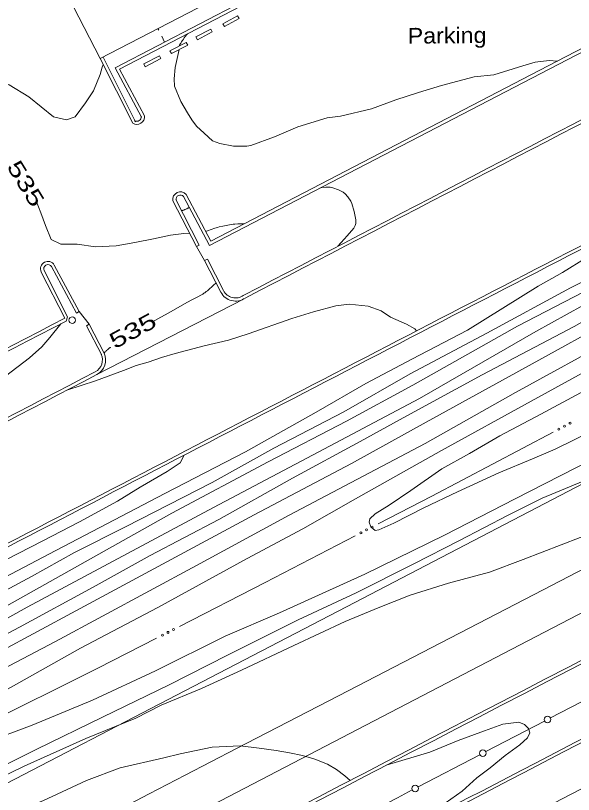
# Model space of a CAD drawing. Extents: x 2361284 to 2366480, y 6976556 to 6985346.
# Drawn here: x 2363068.1 to 2363237.5, y 6978434.8 to 6978671.2 of the extents above; entities that cross this region are included whole.
import ezdxf
from ezdxf.enums import TextEntityAlignment as Align

# ---------------------------------------------------------------- set-up
doc = ezdxf.new("R2010")
doc.units = 0
doc.header["$LTSCALE"] = 1.9
for name, color, linetype, lineweight in [('12', 7, 'Continuous', 13), ('13', 7, 'Continuous', 13), ('14', 7, 'Continuous', 13), ('19', 7, 'Continuous', 13), ('21', 7, 'Continuous', 13), ('3', 7, 'Continuous', 13), ('4', 7, 'Continuous', 13), ('5', 7, 'Continuous', 13), ('7', 7, 'Continuous', 13)]:
    doc.layers.add(name, color=color, linetype=linetype, lineweight=lineweight)

msp = doc.modelspace()

# ---------------------------------------------------------------- linework, layer by layer
at = {"layer": '12'}
for points in [[(2363425.131, 6978674.37), (2363410.482, 6978666.74), (2363395.262, 6978658.375), (2363383.212, 6978651.901), (2363368.635, 6978644.111), (2363350.983, 6978633.733), (2363328, 6978620.233), (2363315.46, 6978613.894), (2363293.258, 6978602.281), (2363261.983, 6978585.954), (2363228.945, 6978567.679), (2363192.752, 6978547.753), (2363170.1, 6978535.207), (2363140.527, 6978519.605), (2363114.03, 6978505.403), (2363086.361, 6978490.518), (2363062.949, 6978478.006), (2363045.723, 6978468.991), (2363032.41, 6978461.884)], [(2363165.952, 6978601.161), (2363166.941, 6978602.34), (2363168.732, 6978604.327), (2363170.761, 6978606.678), (2363171.201, 6978607.487), (2363171.367, 6978608.058), (2363171.407, 6978609.214), (2363170.894, 6978611.689), (2363170.169, 6978614.143), (2363169.862, 6978614.864), (2363168.98, 6978616.191), (2363168.121, 6978617.068), (2363167.485, 6978617.547), (2363166.069, 6978618.324), (2363164.431, 6978618.895), (2363163.58, 6978619.06), (2363162.301, 6978619.138), (2363161.058, 6978618.994), (2363160.464, 6978618.831)], [(2363120.862, 6978605.152), (2363119.104, 6978604.996), (2363115.128, 6978604.568), (2363109.909, 6978603.378), (2363104.248, 6978602.344), (2363098.567, 6978601.27), (2363092.301, 6978600.951), (2363086.763, 6978601.788), (2363081.761, 6978601.81), (2363078.848, 6978603.203), (2363077.108, 6978607.437), (2363075.711, 6978611.254), (2363074.317, 6978614.891)], [(2363120.818, 6978612.943), (2363120.664, 6978612.857), (2363120.586, 6978612.816), (2363120.469, 6978612.755), (2363120.351, 6978612.697), (2363120.291, 6978612.668), (2363120.056, 6978612.558), (2363119.939, 6978612.504), (2363119.762, 6978612.425), (2363119.585, 6978612.346), (2363119.496, 6978612.308), (2363119.317, 6978612.233), (2363119.228, 6978612.196), (2363119.093, 6978612.143), (2363118.912, 6978612.073), (2363118.821, 6978612.04), (2363118.685, 6978611.991), (2363118.547, 6978611.944), (2363118.478, 6978611.921)], [(2363137.387, 6978607.941), (2363136.836, 6978607.98), (2363136.56, 6978607.991), (2363136.146, 6978607.996), (2363135.526, 6978607.973), (2363134.615, 6978607.896), (2363134.161, 6978607.846), (2363133.481, 6978607.759), (2363132.464, 6978607.596), (2363131.449, 6978607.395), (2363130.943, 6978607.279), (2363129.897, 6978607.015), (2363129.379, 6978606.873), (2363128.609, 6978606.647), (2363127.464, 6978606.276), (2363126.331, 6978605.863), (2363125.767, 6978605.639)], [(2363253.996, 6978607.619), (2363253.283, 6978605.821), (2363248.717, 6978602.228), (2363241.34, 6978597.638), (2363234.103, 6978593.16), (2363226.762, 6978589.02), (2363205.247, 6978575.723), (2363188.419, 6978566.924), (2363174.43, 6978559.51), (2363159.371, 6978550.766), (2363137.904, 6978538.791), (2363113.334, 6978526.107), (2363078.126, 6978507.682), (2363030.81, 6978482.841), (2363007.915, 6978470.651)], [(2363109.658, 6978578.215), (2363111.235, 6978579.115), (2363114.403, 6978580.89), (2363120.282, 6978584.147), (2363121.627, 6978584.875), (2363123.426, 6978585.835), (2363124.321, 6978586.325), (2363124.887, 6978586.66), (2363125.254, 6978586.898), (2363125.495, 6978587.063), (2363125.967, 6978587.407), (2363126.314, 6978587.675), (2363126.992, 6978588.234), (2363127.652, 6978588.818), (2363128.084, 6978589.217), (2363128.937, 6978590.029)], [(2363189.808, 6978575.477), (2363189.331, 6978576.142), (2363186.748, 6978577.508), (2363181.918, 6978579.622), (2363179.09, 6978581.515), (2363175.077, 6978582.957), (2363169.319, 6978583.612), (2363165.314, 6978583.094), (2363158.531, 6978581.279), (2363151.92, 6978579.206), (2363138.644, 6978574.57), (2363132.732, 6978572.664), (2363125.327, 6978570.923), (2363116.509, 6978568.639), (2363112.391, 6978567.441), (2363108.304, 6978566.012), (2363104.684, 6978564.988), (2363100.797, 6978563.481), (2363092.277, 6978560.329), (2363083.644, 6978557.476)], [(2363094.957, 6978568.754), (2363095.165, 6978568.978), (2363095.27, 6978569.089), (2363095.428, 6978569.254), (2363095.588, 6978569.416), (2363095.669, 6978569.497), (2363095.833, 6978569.655), (2363095.916, 6978569.733), (2363096.043, 6978569.847), (2363096.157, 6978569.947), (2363096.215, 6978569.997), (2363096.302, 6978570.069), (2363096.436, 6978570.176), (2363096.572, 6978570.28), (2363096.641, 6978570.331), (2363096.736, 6978570.398), (2363096.8, 6978570.441), (2363096.843, 6978570.469), (2363096.901, 6978570.505), (2363096.93, 6978570.523)], [(2363245.276, 6978515.02), (2363222.22, 6978506.112), (2363212.015, 6978502.204), (2363199.518, 6978498.865), (2363187.89, 6978495.285), (2363178.197, 6978491.441), (2363168.135, 6978487.266), (2363152.574, 6978479.938), (2363136.654, 6978472.546), (2363124.526, 6978466.89), (2363112.284, 6978461.853), (2363104.621, 6978457.97), (2363089.379, 6978451.756), (2363070.637, 6978443.367), (2363050.648, 6978433.696)]]:
    msp.add_lwpolyline(points, dxfattribs=at)
at = {"layer": '13'}
for points in [[(2363466.464, 6978693.163), (2363427.882, 6978671.135), (2363406.518, 6978659.812), (2363378.846, 6978645.158), (2363355.135, 6978632.452), (2363330.817, 6978619.5), (2363302.789, 6978603.332), (2363273.639, 6978586.335), (2363250.48, 6978573.553), (2363219.818, 6978556.721), (2363192.452, 6978541.33), (2363151.159, 6978519.537), (2363122.982, 6978504.268), (2363080.158, 6978481.2), (2363045.956, 6978463.343), (2363028.606, 6978453.868), (2362997.225, 6978435.868)], [(2363471.837, 6978691.884), (2363433.081, 6978669.065), (2363388.829, 6978643.763), (2363361.558, 6978630.143), (2363335.038, 6978616.29), (2363304.423, 6978598.767), (2363283.358, 6978586.648), (2363254.449, 6978570.531), (2363224.593, 6978554.106), (2363197.365, 6978539.137), (2363171.312, 6978524.538), (2363155.277, 6978515.405), (2363138.423, 6978506.345), (2363111.253, 6978491.475), (2363087.769, 6978479.162), (2363067.447, 6978467.717), (2363051.708, 6978459.007), (2363041.356, 6978452.82), (2363025.578, 6978443.038), (2363017.156, 6978436.918)], [(2363404.842, 6978677.178), (2363386.759, 6978666.934), (2363370.561, 6978658.34), (2363349.169, 6978646.756), (2363326.951, 6978634.904), (2363305.503, 6978622), (2363284.28, 6978610.557), (2363263.345, 6978599.367), (2363243.325, 6978588.707), (2363220.507, 6978576.858), (2363188.725, 6978558.956), (2363168.577, 6978548.073), (2363144.804, 6978535.717), (2363115.53, 6978520.148), (2363063.804, 6978491.124), (2363027.404, 6978471.927), (2362989.536, 6978451.437)], [(2363420.847, 6978676.89), (2363400.664, 6978665.546), (2363383.778, 6978656.545), (2363364.35, 6978646.78), (2363346.604, 6978637.691), (2363320.48, 6978623.292), (2363297.872, 6978610.297), (2363272.542, 6978596.555), (2363249.823, 6978583.698), (2363237.629, 6978576.751), (2363209.735, 6978562.136), (2363186.853, 6978549.667), (2363172.647, 6978541.912), (2363152.141, 6978530.756), (2363129.77, 6978518.193), (2363108.943, 6978507.265), (2363091.583, 6978497.669), (2363069.237, 6978485.515), (2363053.812, 6978477.479), (2363033.78, 6978467.117), (2363018.575, 6978459.122), (2362992.386, 6978445.153)], [(2363411.158, 6978675.608), (2363398.63, 6978669.077), (2363374.655, 6978656.739), (2363360.176, 6978649.281), (2363331.118, 6978634.134), (2363304.774, 6978618.643), (2363274.153, 6978601.67), (2363249.808, 6978588.469), (2363226.012, 6978575.331), (2363190.672, 6978554.994), (2363156.533, 6978536.848), (2363128.204, 6978521.888), (2363071.559, 6978491.597), (2363048.758, 6978478.971), (2362991.135, 6978448.391)], [(2363375.65, 6978670.939), (2363375.344, 6978669.496), (2363373.266, 6978667.316), (2363369.52, 6978664.62), (2363363.374, 6978660.992), (2363358.271, 6978658.133), (2363348.567, 6978652.291), (2363333.03, 6978642.352), (2363312.867, 6978631.06), (2363295.42, 6978621.024), (2363282.312, 6978613.489), (2363251.326, 6978596.013), (2363236.606, 6978588.503), (2363211.206, 6978574.75), (2363187.872, 6978562.399), (2363167.69, 6978550.905), (2363146.465, 6978539.844), (2363127.722, 6978529.504), (2363101.439, 6978515.953), (2363085.992, 6978508.236), (2363072.94, 6978500.912), (2363041.639, 6978484.123), (2362987.669, 6978454.279)], [(2363117.703, 6978661.906), (2363117.802, 6978662.085), (2363117.868, 6978662.204), (2363118.004, 6978662.441), (2363118.073, 6978662.558), (2363118.213, 6978662.792), (2363118.356, 6978663.024), (2363118.452, 6978663.178), (2363118.648, 6978663.485), (2363118.811, 6978663.733), (2363118.921, 6978663.897), (2363118.996, 6978664.005), (2363119.146, 6978664.22), (2363119.261, 6978664.381), (2363119.338, 6978664.487), (2363119.494, 6978664.698), (2363119.573, 6978664.803), (2363119.733, 6978665.012), (2363119.895, 6978665.219), (2363120.005, 6978665.357), (2363120.078, 6978665.448), (2363120.227, 6978665.63)], [(2363232.572, 6978657.318), (2363230.07, 6978657.514), (2363225.815, 6978657.024), (2363222.115, 6978655.918), (2363213.32, 6978653.145), (2363207.335, 6978652.579), (2363197.351, 6978649.923), (2363190.44, 6978647.807), (2363183.57, 6978645.641), (2363176.147, 6978642.871), (2363166.737, 6978640.681), (2363162.651, 6978640.162), (2363153.717, 6978637.427), (2363146.646, 6978634.37), (2363139.471, 6978631.722), (2363138.293, 6978631.5), (2363134.212, 6978631.501), (2363130.055, 6978632.312), (2363127.877, 6978633.101), (2363125.334, 6978635.427), (2363123.043, 6978637.566), (2363121.566, 6978639.502), (2363120.306, 6978641.63), (2363118.252, 6978645.11), (2363116.348, 6978649.732), (2363116.177, 6978651.952), (2363116.474, 6978655.444), (2363117.743, 6978660.846)], [(2363094.663, 6978656.357), (2363094.301, 6978655.543), (2363093.744, 6978653.288), (2363091.681, 6978648.288), (2363089.285, 6978644.685), (2363086.175, 6978640.485), (2363083.544, 6978639.5), (2363079.544, 6978640.402), (2363072.066, 6978646.551), (2363066.102, 6978650.185), (2363062.282, 6978652.239), (2363058.378, 6978654.602), (2363055.115, 6978657.021), (2363048.092, 6978659.444)], [(2363416.648, 6978618.916), (2363397.786, 6978610.617), (2363380.297, 6978602.909), (2363363.089, 6978595.286), (2363343.764, 6978585.172), (2363322.354, 6978575.507), (2363296.819, 6978562.324), (2363267.053, 6978548.07), (2363247.313, 6978538.522), (2363219.785, 6978524.489), (2363198.288, 6978513.493), (2363174.07, 6978501.614), (2363148.229, 6978489.916), (2363131.686, 6978482.83), (2363110.495, 6978472.297), (2363091.408, 6978463.445), (2363073.079, 6978455.781), (2363058.908, 6978450.595)], [(2363081.821, 6978577.62), (2363078.501, 6978573.438), (2363076.077, 6978570.645), (2363072.309, 6978567.27), (2363064.993, 6978561.73), (2363053.641, 6978554.361), (2363045.787, 6978548.506), (2363038.227, 6978542.254), (2363024.622, 6978533.124), (2363013.072, 6978526.674), (2362997.711, 6978518.358), (2362987.423, 6978512.718), (2362976.815, 6978507.348), (2362964.075, 6978500.827)], [(2363243.021, 6978545.031), (2363231.952, 6978539.617), (2363225.07, 6978536.63), (2363214.81, 6978532.382), (2363202.284, 6978526.593), (2363192.048, 6978521.775), (2363182.883, 6978517.077), (2363178.312, 6978515.084), (2363177.214, 6978514.863), (2363175.934, 6978515.961), (2363175.471, 6978517.367), (2363175.671, 6978518.42), (2363177.266, 6978519.955), (2363181.45, 6978522.605), (2363188.069, 6978526.998), (2363197.507, 6978533.598), (2363205.923, 6978538.298), (2363215.103, 6978543.636), (2363227.601, 6978550.145), (2363249.022, 6978561.74)], [(2363119.293, 6978537.764), (2363118.025, 6978535.462), (2363114.06, 6978532.764), (2363105.925, 6978528.057), (2363098.984, 6978523.811), (2363087.474, 6978517.541), (2363076.287, 6978511.744), (2363054.005, 6978500.292), (2363036.704, 6978490.886), (2363022.436, 6978483.261), (2363009.254, 6978476.035), (2363003.792, 6978473.092)], [(2363240.425, 6978529.836), (2363227.963, 6978524.677), (2363217.652, 6978519.539), (2363202.834, 6978511.858), (2363189, 6978504.726), (2363171.504, 6978495.999), (2363153.82, 6978487.769), (2363132.36, 6978477.096), (2363114.715, 6978468.097), (2363094.498, 6978458.194), (2363074.508, 6978448.524), (2363054.502, 6978438.573)], [(2363182.847, 6978421.912), (2363187.406, 6978425.196), (2363193.554, 6978428.755), (2363198.462, 6978432.141), (2363203.617, 6978435.801), (2363208.109, 6978439.833), (2363212.209, 6978442.873), (2363216.745, 6978446.606), (2363221.185, 6978449.818), (2363223.455, 6978451.941), (2363224.22, 6978453.478), (2363223.858, 6978454.785), (2363222.626, 6978456.023), (2363220.849, 6978456.706), (2363216.025, 6978456.12), (2363210.483, 6978454.098), (2363202.401, 6978451.171), (2363193.834, 6978447.648), (2363180.621, 6978443.642)], [(2363169.644, 6978439.028), (2363168.061, 6978440.423), (2363165.522, 6978442.359), (2363162.777, 6978443.943), (2363158.882, 6978445.526), (2363155.212, 6978446.551), (2363151.265, 6978447.363), (2363147.207, 6978448.075), (2363141.98, 6978448.835), (2363136.223, 6978449.49), (2363127.796, 6978449.1), (2363117.985, 6978447.087), (2363113.086, 6978445.94), (2363099.794, 6978442.824), (2363089.621, 6978439.017), (2363076.307, 6978432.87), (2363060.476, 6978426.739), (2363049.242, 6978422.762), (2363035.932, 6978417.435), (2363021.666, 6978411.769), (2363012.303, 6978407.75)]]:
    msp.add_lwpolyline(points, dxfattribs=at)
at = {"layer": '14'}
for points in [[(2363949.629, 6978887.968), (2363929.935, 6978874.907), (2363890.416, 6978848.983), (2363868.159, 6978834.534), (2363853.276, 6978824.971), (2363823.411, 6978805.994), (2363812.654, 6978799.246), (2363791.042, 6978785.916), (2363769.312, 6978772.782), (2363754.767, 6978764.121), (2363725.557, 6978746.99), (2363693.768, 6978728.641), (2363677.819, 6978719.566), (2363653.804, 6978706.125), (2363629.648, 6978692.939), (2363617.507, 6978686.459), (2363544.112, 6978647.817), (2363507.33, 6978628.659), (2363367.402, 6978556.134), (2363223.565, 6978481.393), (2363026.986, 6978379.118)], [(2363951.494, 6978832.723), (2363916.041, 6978809.685), (2363857.621, 6978772.577), (2363781.115, 6978725.377), (2363714.322, 6978686.016), (2363680.485, 6978667.097), (2363570.079, 6978608.155), (2363462.054, 6978552.184), (2363320.548, 6978478.375), (2363145.373, 6978387.445), (2363047.939, 6978336.875)], [(2363021.389, 6978389.336), (2363050.467, 6978404.567), (2363065.01, 6978412.173), (2363086.833, 6978423.568), (2363108.666, 6978434.943), (2363119.587, 6978440.622), (2363135.102, 6978448.676), (2363166.147, 6978464.756), (2363228.252, 6978496.885), (2363248.945, 6978507.613), (2363259.287, 6978512.984), (2363294.18, 6978531.142), (2363340.693, 6978555.376), (2363363.954, 6978567.483), (2363374.788, 6978573.111), (2363396.467, 6978584.346), (2363439.836, 6978606.794), (2363461.508, 6978618.043), (2363470.134, 6978622.537), (2363475.881, 6978625.539), (2363487.368, 6978631.558), (2363504.583, 6978640.615), (2363516.051, 6978646.668), (2363538.975, 6978658.801)]]:
    msp.add_lwpolyline(points, dxfattribs=at)
at = {"layer": '19'}
for p, q in [((2363111.547, 6978666.688), (2363111.282, 6978667.225)), ((2363113.301, 6978663.104), (2363112.424, 6978664.896))]:
    msp.add_line(p, q, dxfattribs=at)
at = {"layer": '21'}
for points in [[(2363231.253, 6978544.749), (2363194.436, 6978525.328), (2363178.125, 6978516.862)], [(2363171.17, 6978513.246), (2363143.832, 6978499.056), (2363117.837, 6978485.757)], [(2363110.861, 6978482.192), (2363093.057, 6978473.091), (2363057.244, 6978455.271)]]:
    msp.add_lwpolyline(points, dxfattribs=at)
for centre in [(2363234.716, 6978546.575), (2363236.415, 6978547.471), (2363233.018, 6978545.679), (2363176.348, 6978515.937), (2363172.94, 6978514.168), (2363174.644, 6978515.053), (2363116.05, 6978484.849), (2363112.631, 6978483.101), (2363114.341, 6978483.975)]:
    msp.add_circle(centre, 0.3, dxfattribs=at)
at = {"layer": '3'}
for p, q in [((2363135.441, 6978671.133), (2363130.984, 6978668.69)), ((2363135.906, 6978670.293), (2363131.449, 6978667.851)), ((2363135.441, 6978671.133), (2363135.906, 6978670.293)), ((2363127.338, 6978667.036), (2363122.801, 6978664.672)), ((2363127.338, 6978667.036), (2363127.786, 6978666.187)), ((2363130.984, 6978668.69), (2363131.449, 6978667.851)), ((2363122.801, 6978664.672), (2363123.249, 6978663.823)), ((2363127.786, 6978666.187), (2363123.249, 6978663.823)), ((2363119.886, 6978663.034), (2363114.94, 6978660.487)), ((2363120.331, 6978662.184), (2363115.384, 6978659.636)), ((2363119.886, 6978663.034), (2363120.331, 6978662.184)), ((2363114.94, 6978660.487), (2363115.384, 6978659.636)), ((2363111.745, 6978658.947), (2363106.989, 6978656.471)), ((2363112.193, 6978658.097), (2363107.436, 6978655.622)), ((2363111.745, 6978658.947), (2363112.193, 6978658.097)), ((2363106.989, 6978656.471), (2363107.436, 6978655.622)), ((2363126.298, 6978597.274), (2363125.441, 6978596.836)), ((2363137.453, 6978585.23), (2363092.719, 6978562.204)), ((2363137.213, 6978586.224), (2363137.325, 6978586.293)), ((2363137.771, 6978585.442), (2363137.768, 6978585.441)), ((2363086.542, 6978580.875), (2363087.387, 6978581.323)), ((2363090.404, 6978577.482), (2363087.387, 6978581.323)), ((2363089.548, 6978577.033), (2363090.404, 6978577.482)), ((2363187.36, 6978574.214), (2363187.357, 6978574.212)), ((2363187.801, 6978573.361), (2363187.8, 6978573.36)), ((2363092.274, 6978563.054), (2363092.267, 6978563.05)), ((2363092.718, 6978562.202), (2363092.719, 6978562.203))]:
    msp.add_line(p, q, dxfattribs=at)
for points in [[(2363011.072, 6978409.979), (2363168.573, 6978491.77), (2363368.216, 6978595.675), (2363555.651, 6978691.931), (2363594.46, 6978712.53), (2363671.163, 6978755.453), (2363729.15, 6978790.847), (2363782.829, 6978826.545), (2363808.985, 6978845.429), (2363827.885, 6978860.013), (2363864.479, 6978890.628), (2363923.502, 6978944.293), (2363947.382, 6978968.611)], [(2363106.232, 6978640.619), (2363106.338, 6978640.307), (2363098.343, 6978655.322), (2363175.407, 6978695.437), (2363288.34, 6978753.653), (2363332.165, 6978776.451), (2363340.338, 6978761.439), (2363343.881, 6978763.293), (2363343.933, 6978763.321)], [(2363107.182, 6978640.755), (2363107.183, 6978640.755), (2363099.647, 6978654.914), (2363175.846, 6978694.581), (2363288.778, 6978752.798), (2363331.777, 6978775.167), (2363339.951, 6978760.154), (2363344.329, 6978762.447), (2363344.329, 6978762.446)], [(2363353.066, 6978738.291), (2363353.007, 6978738.457), (2363360.778, 6978722.661), (2363232.792, 6978656.35), (2363126.908, 6978601.42), (2363118.985, 6978616.416), (2363119.095, 6978616.247)], [(2363352.142, 6978738.029), (2363352.141, 6978738.029), (2363359.504, 6978723.079), (2363232.354, 6978657.206), (2363127.316, 6978602.714), (2363119.831, 6978616.864), (2363119.831, 6978616.864)], [(2363093.757, 6978658.158), (2363103.643, 6978638.521), (2363103.644, 6978638.521)], [(2363094.612, 6978658.586), (2363104.5, 6978638.949), (2363104.175, 6978639.321)], [(2363115.851, 6978614.946), (2363115.849, 6978614.946), (2363122.95, 6978601.072)], [(2363116.791, 6978615.137), (2363116.705, 6978615.384), (2363123.806, 6978601.51)], [(2363123.806, 6978601.51), (2363122.95, 6978601.072), (2363125.441, 6978596.836)], [(2363125.441, 6978596.836), (2363130.363, 6978587.243), (2363130.363, 6978587.242)], [(2363126.298, 6978597.274), (2363131.219, 6978587.681), (2363131.217, 6978587.681)], [(2363076.738, 6978593.756), (2363076.728, 6978593.773), (2363083.842, 6978579.739), (2363083.426, 6978578.448)], [(2363086.542, 6978580.875), (2363078.976, 6978595.015), (2363078.996, 6978594.973)], [(2363087.387, 6978581.323), (2363079.822, 6978595.463), (2363079.822, 6978595.462)], [(2363075.875, 6978593.336), (2363075.872, 6978593.335), (2363082.986, 6978579.301), (2363082.985, 6978579.301)], [(2363094.958, 6978568.755), (2363094.957, 6978568.754), (2363090.404, 6978577.482)], [(2363094.082, 6978568.362), (2363094.102, 6978568.306), (2363089.548, 6978577.033)]]:
    msp.add_lwpolyline(points, dxfattribs=at)
for centre, radius, start, end in [((2446851.432, 6817441.355), 181592.243, 117.35268, 117.45168), ((2446851.433, 6817441.355), 181591.283, 117.35268, 117.45168), ((2342834.51, 7017985.293), 44356.191, 297.31294, 297.61226), ((2342834.51, 7017985.293), 44357.151, 297.31294, 297.61226), ((2510756.167, 6694462.226), 320038.438, 117.37709, 117.46624), ((2510756.166, 6694462.227), 320037.476, 117.37709, 117.46624), ((2363104.912, 6978640.431), 2.293, 236.42127, 8.10639), ((2363104.912, 6978640.431), 1.333, 236.42125, 8.10637), ((2363118.084, 6978615.399), 2.279, 39.98858, 191.45927), ((2363118.084, 6978615.399), 1.319, 39.98858, 191.45927), ((2363077.892, 6978594.319), 2.244, 30.64163, 205.97974), ((2363077.892, 6978594.319), 1.284, 30.64164, 205.97975), ((2363134.845, 6978589.546), 5.04, 207.20297, 305.48306), ((2363134.845, 6978589.546), 4.08, 207.20298, 305.48306), ((2416815.134, 6874672.847), 116977.327, 117.34441, 117.41385), ((2416815.134, 6874672.849), 116976.366, 117.34441, 117.41385), ((2290091.034, 7119171.363), 158463.343, 297.386, 297.46988), ((2290091.035, 7119171.361), 158464.302, 297.386, 297.46988), ((2363090.327, 6978566.679), 4.115, 298.12336, 24.15065), ((2363090.327, 6978566.679), 5.075, 298.12336, 24.15065), ((2341888.702, 7019227.765), 45860.77, 297.36056, 297.53863), ((2341888.701, 7019227.765), 45861.73, 297.36056, 297.53863), ((2341214.887, 7020680.278), 47627.312, 297.27734, 297.63097), ((2341214.887, 7020680.278), 47628.272, 297.27734, 297.63097)]:
    msp.add_arc(centre, radius, start, end, dxfattribs=at)
at = {"layer": '4'}
msp.add_circle((2363085.275, 6978578.733), 1, dxfattribs=at)
at = {"layer": '5'}
for p, q in [((2363249.166, 6978467.735), (2363230.438, 6978457.987)), ((2363228.676, 6978457.071), (2363210.823, 6978447.77)), ((2363209.002, 6978446.822), (2363190.274, 6978437.074))]:
    msp.add_line(p, q, dxfattribs=at)
msp.add_lwpolyline([(2363188.512, 6978436.157), (2363183.984, 6978433.804), (2363170.651, 6978426.877)], dxfattribs=at)
for centre in [(2363229.559, 6978457.527), (2363209.938, 6978447.313), (2363189.394, 6978436.619)]:
    msp.add_circle(centre, 1, dxfattribs=at)
at = {"layer": '7'}
msp.add_lwpolyline([(2363054.534, 6978733.96), (2363093.757, 6978658.158), (2363253.908, 6978741.025), (2363251.687, 6978745.325), (2363286.667, 6978763.399), (2363281.899, 6978772.633), (2363321.993, 6978793.336), (2363211.982, 6979006.392), (2363135.971, 6978967.146), (2363213.89, 6978816.239)], close=True, dxfattribs=at)

# ---------------------------------------------------------------- texts
at = {"layer": '12', "width": 1.4}
for rotation, p in [(301.554, (2363069.13, 6978618.943)), (28.509, (2363104.776, 6978573.432))]:
    msp.add_text(' 535 ', height=4.8, rotation=rotation, dxfattribs=at).set_placement(p, align=Align.CENTER)
at = {"layer": '3', "width": 1.1}
msp.add_text('Parking', height=4.799, rotation=0.545, dxfattribs=at).set_placement((2363187.139, 6978662.626))

doc.saveas('drawing.dxf')
